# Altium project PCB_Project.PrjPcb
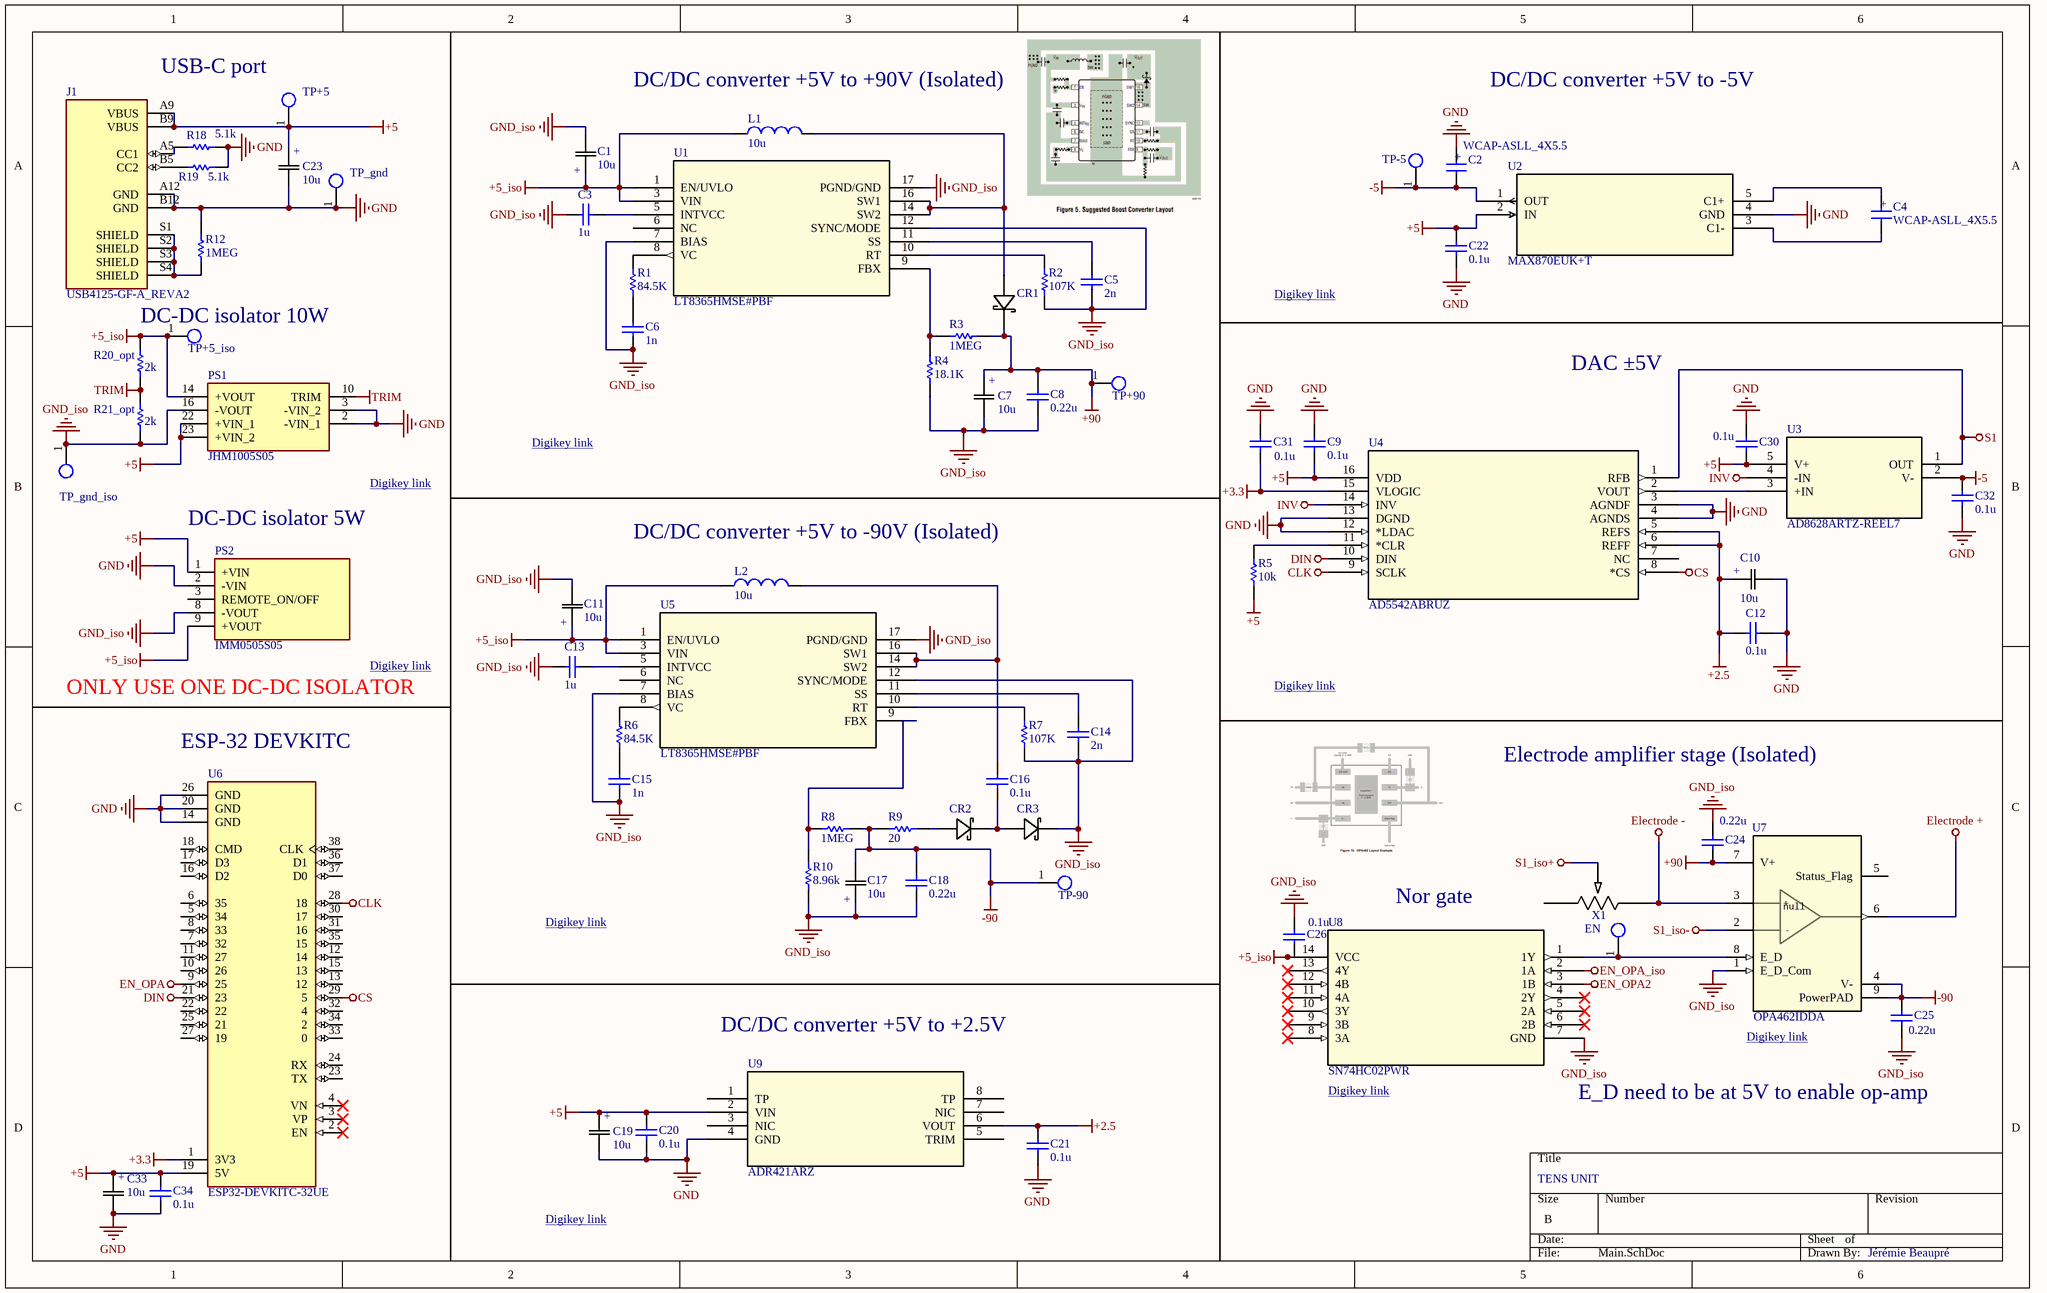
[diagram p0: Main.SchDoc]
3 sheets, 104 parts. Net scope: global (net labels, ports and power ports of the same name join across sheets).
Board file: PCB1.PcbDoc
Sheets:
  Main.SchDoc
  Current_check.SchDoc
  Isolation.SchDoc

## Sheet Main.SchDoc
size B; SheetNumber: 1; SheetTotal: 3

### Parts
C1  10u  [CAP_BX_10x20_RUB]
C2  WCAP-ASLL_4X5.5  [WCAP-ASLL_4X5.5(DXL)]
C3  value 1u  [0805_AVX]  (hidden comment: Capacitor)
C4  WCAP-ASLL_4X5.5  [WCAP-ASLL_4X5.5(DXL)]
C5  value 2n  [CAPC2012X75N]  (hidden comment: Capacitor)
C6  value 1n  [CC0805N_YAG]  (hidden comment: Capacitor)
C7  10u  [CAP_BX_10x20_RUB]
C8  value 0.22u  [CAP_C3225X7R2E224K200AA]  (hidden comment: Capacitor)
C9  value 0.1u  [CAPC2012X150N]  (hidden comment: Capacitor)
C10  10u  [CAP_BX_10x20_RUB]
C11  10u  [CAP_BX_10x20_RUB]
C12  value 0.1u  [CAPC2012X150N]  (hidden comment: Capacitor)
C13  value 1u  [0805_AVX]  (hidden comment: Capacitor)
C14  value 2n  [CAPC2012X75N]  (hidden comment: Capacitor)
C15  value 1n  [CC0805N_YAG]  (hidden comment: Capacitor)
C16  value 0.1u  [CAPC2012X150N]  (hidden comment: Capacitor)
C17  10u  [CAP_BX_10x20_RUB]
C18  value 0.22u  [CAP_C3225X7R2E224K200AA]  (hidden comment: Capacitor)
C19  10u  [CAP_BX_10x20_RUB]
C20  value 0.1u  [CAPC2012X150N]  (hidden comment: Capacitor)
C21  value 0.1u  [CAPC2012X150N]  (hidden comment: Capacitor)
C22  value 0.1u  [CAPC2012X150N]  (hidden comment: Capacitor)
C23  10u  [CAP_BX_10x20_RUB]
C24  value 0.22u  [CAP_C3225X7R2E224K200AA]  (hidden comment: Capacitor)
C25  value 0.22u  [CAP_C3225X7R2E224K200AA]  (hidden comment: Capacitor)
C26  value 0.1u  [CAPC2012X150N]  (hidden comment: Capacitor)
C30  value 0.1u  [CAPC2012X150N]  (hidden comment: Capacitor)
C31  value 0.1u  [CAPC2012X150N]  (hidden comment: Capacitor)
C32  value 0.1u  [CAPC2012X150N]  (hidden comment: Capacitor)
C33  10u  [CAP_BX_10x20_RUB]
C34  value 0.1u  [CAPC2012X150N]  (hidden comment: Capacitor)
CR1  SK220ATR  [DIODE_SK220ATR_SMC-M]  (value not drawn)
CR2  SK220ATR  [DIODE_SK220ATR_SMC-M]  (value not drawn)
CR3  SK220ATR  [DIODE_SK220ATR_SMC-M]  (value not drawn)
EN  Testpoint_1  [Testpoint1]  (value not drawn)  (no BOM)
J1  USB4125-GF-A_REVA2  [GCT_USB4125-GF-A_REVA2]
L1  value 10u  [DR73]  (hidden comment: Inductor)
L2  value 10u  [DR73]  (hidden comment: Inductor)
PS1  JHM1005S05  [JHM1005S05]
PS2  IMM0505S05  [IMM0505S05]
R1  value 84.5K  [Resistor_0805-M]  (hidden comment: Resistor)
R2  value 107K  [Resistor_0805-M]  (hidden comment: Resistor)
R3  value 1MEG  [Resistor_0805-M]  (hidden comment: Resistor)
R4  value 18.1K  [Resistor_0805-M]  (hidden comment: Resistor)
R5  value 10k  [Resistor_0805-M]  (hidden comment: Resistor)
R6  value 84.5K  [Resistor_0805-M]  (hidden comment: Resistor)
R7  value 107K  [Resistor_0805-M]  (hidden comment: Resistor)
R8  1MEG  [Resistor_0805-M]
R9  value 20  [Resistor_0805-M]  (hidden comment: Resistor)
R10  value 8.96k  [Resistor_0805-M]  (hidden comment: Resistor)
R12  value 1MEG  [Resistor_0805-M]  (hidden comment: Resistor)
R18  value 5.1k  [Resistor_0805-M]  (hidden comment: Resistor)
R19  value 5.1k  [Resistor_0805-M]  (hidden comment: Resistor)
R20_opt  value 2k  [Resistor_0805-M]  (hidden comment: Resistor)
R21_opt  value 2k  [Resistor_0805-M]  (hidden comment: Resistor)
TP+5  Testpoint_1  [Testpoint1]  (value not drawn)  (no BOM)
TP+5_iso  Testpoint_1  [Testpoint1]  (value not drawn)  (no BOM)
TP+90  Testpoint_1  [Testpoint1]  (value not drawn)  (no BOM)
TP-5  Testpoint_1  [Testpoint1]  (value not drawn)  (no BOM)
TP-90  Testpoint_1  [Testpoint1]  (value not drawn)  (no BOM)
TP_gnd  Testpoint_1  [Testpoint1]  (value not drawn)  (no BOM)
TP_gnd_iso  Testpoint_1  [Testpoint1]  (value not drawn)  (no BOM)
U1  LT8365HMSE#PBF  [05-08-1871_ADI]
U2  MAX870EUK+T  [21-0057F_MXM]
U3  AD8628ARTZ-REEL7  [RJ_5_ADI]
U4  AD5542ABRUZ  [RU_16_ADI]
U5  LT8365HMSE#PBF  [05-08-1871_ADI]
U6  ESP32-DEVKITC-32UE  [ESPRESSIF_ESP32-DEVKITC-32UE]
U7  OPA462IDDA  [DDA0008J-IPC_A]
U8  SN74HC02PWR  [PW14]
U9  ADR421ARZ  [R_8_ADI]
X1  PV36W102C01B00  [POT_PV36W_MUR]  (value not drawn)

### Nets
+2.5: C10.1(+) C12.2 C21.2 U4.5(REFS) U4.6(REFF) U9.6(VOUT)
+3.3: C31.2 U4.15(VLOGIC) U6.1(3V3)
+5: C9.2 C19.1(+) C20.2 C22.1 C23.1(+) C30.2 C33.1(+) C34.2 J1.A9(VBUS) J1.B9(VBUS) PS1.22(+VIN_1) PS1.23(+VIN_2) PS2.1(+VIN) R5.1 TP+5.1(P1) U2.2(IN) U3.5(V+) U4.16(VDD) U6.19(5V) U9.2(VIN)
+5_iso: C1.1(+) C11.1(+) C26.1 L1.1 L2.1 PS1.14(+VOUT) PS2.9(+VOUT) R20_opt.1 TP+5_iso.1(P1) U1.1(EN/UVLO) U1.3(VIN) U5.1(EN/UVLO) U5.3(VIN) U8.14(VCC)
+90: C7.1(+) C8.2 C24.2 CR1.1 R3.2 TP+90.1(P1) U7.7(V+)
-5: C2.2(NEG) C32.2 TP-5.1(P1) U2.1(OUT) U3.2(V-)
-90: C17.2 C18.2 C25.1 R8.1 R9.2 TP-90.1(P1) U7.4(V-) U7.9(PowerPAD)
CLK: U4.9(SCLK) U6.28(18)
CS: U4.8(*CS) U6.29(5)
DIN: U4.10(DIN) U6.21(23)
Electrode +: U7.6(OUT)
Electrode -: U7.3(+IN) X1.3
EN_OPA: U6.9(25)
EN_OPA2: U8.3(1B)
EN_OPA_iso: U8.2(1A)
GND: C2.1(POS) C9.1 C10.2 C12.1 C19.2 C20.1 C21.1 C22.2 C23.2 C30.1 C31.1 C32.1 C33.2 C34.1 J1.A12(GND) J1.B12(GND) PS1.2(-VIN_1) PS1.3(-VIN_2) PS2.2(-VIN) R12.2 R18.1 R19.1 TP_gnd.1(P1) U2.4(GND) U4.3(AGNDF) U4.4(AGNDS) U4.12(*LDAC) U4.13(DGND) U6.14(GND) U6.20(GND) U6.26(GND) U9.4(GND)
GND_iso: C1.2 C3.2 C5.1 C6.1 C7.2 C8.1 C11.2 C13.2 C14.1 C15.1 C17.1(+) C18.1 C24.1 C25.2 C26.2 CR3.1 PS1.16(-VOUT) PS2.8(-VOUT) R2.1 R4.2 R7.1 R10.2 R21_opt.2 TP_gnd_iso.1(P1) U1.7(BIAS) U1.12(SYNC/MODE) U1.17(PGND/GND) U5.7(BIAS) U5.12(SYNC/MODE) U5.17(PGND/GND) U7.1(E_D_Com) U8.7(GND)
INV: U3.4(-IN) U4.14(INV)
S1: U3.1(OUT) U4.1(RFB)
S1_iso+: X1.2
S1_iso-: U7.2(-IN)
TRIM: PS1.10(TRIM) R20_opt.2 R21_opt.1
NetC3_1: C3.1 U1.5(INTVCC)
NetC4_1: C4.1(POS) U2.5(C1+)
NetC4_2: C4.2(NEG) U2.3(C1-)
NetC5_2: C5.2 U1.11(SS)
NetC6_2: C6.2 R1.1
NetC13_1: C13.1 U5.5(INTVCC)
NetC14_2: C14.2 U5.11(SS)
NetC15_2: C15.2 R6.1
NetC16_1: C16.1 CR2.1 CR3.2
NetC16_2: C16.2 L2.2 U5.14(SW2) U5.16(SW1)
NetCR1_2: CR1.2 L1.2 U1.14(SW2) U1.16(SW1)
NetCR2_2: CR2.2 R9.1
NetEN_1: EN.1(P1) U7.8(E_D) U8.1(1Y)
NetJ1_A5: J1.A5(CC1) R18.2
NetJ1_B5: J1.B5(CC2) R19.2
NetJ1_S1: J1.S1(SHIELD) J1.S2(SHIELD) J1.S3(SHIELD) J1.S4(SHIELD) R12.1
NetR1_2: R1.2 U1.8(VC)
NetR2_2: R2.2 U1.10(RT)
NetR3_1: R3.1 R4.1 U1.9(FBX)
NetR5_2: R5.2 U4.11(*CLR)
NetR6_2: R6.2 U5.8(VC)
NetR7_2: R7.2 U5.10(RT)
NetR8_2: R8.2 R10.1 U5.9(FBX)
NetU3_3: U3.3(+IN) U4.2(VOUT)

Not connected (* = marked no-connect by the designer): PS2 3(REMOTE_ON/OFF); U1 6(NC); U4 7(NC); U5 6(NC); U6 2(EN)* 3(VP)* 4(VN)* 5(34) 6(35) 7(32) 8(33) 10(26) 11(27) 12(14) 13(12) 15(13) 16(D2) 17(D3) 18(CMD) 22 23(TX) 24(RX) 25(21) 27(19) 30(17) 31(16) 32(4) 33(0) 34(2) 35(15) 36(D1) 37(D0) 38(CLK); U7 5(Status_Flag); U8 4(2Y)* 5(2A)* 6(2B)* 8(3A)* 9(3B)* 10(3Y)* 11(4A)* 12(4B)* 13(4Y)*; U9 1(TP) 3(NIC) 5(TRIM) 7(NIC) 8(TP); X1 1

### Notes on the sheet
- USB-C port
- (near L1) DC/DC converter +5V to +90V (Isolated)
- DC/DC converter +5V to -5V
- Digikey link <https://www.digikey.ca/en/products/detail/analog-devices-inc-maxim-integrated/MAX870EUK-T/1519059?_gl=1*bc40r*_up*MQ..*_gs*MQ..&gclid=Cj0KCQjwm8bTBhDWARIsAC9Hi8lZmiOB0El9-E_6c1ow4nDcjeTHfbqA0Lnjgy8U8yTUWBJwg5PWeQ0aAiB7EALw_wcB&gclsrc=aw.ds&gbraid=0AAAAADrbLlh2Yqokbm2Ifr7gOHjBvqx8v>
- (near TP+5_iso) DC-DC isolator 10W
- DAC ±5V
- Digikey link <https://www.digikey.ca/en/products/detail/xp-power/JHM1005S05/4488429?s=N4IgTCBcDaIFYAsC2BGADGgrAZyyAugL5A>
- Digikey link <https://www.digikey.ca/en/products/detail/analog-devices-inc/LT8365HMSE-PBF/11586882?_gl=1*1sgahmh*_up*MQ..*_gs*MQ..&gclid=Cj0KCQjwm8bTBhDWARIsAC9Hi8lZmiOB0El9-E_6c1ow4nDcjeTHfbqA0Lnjgy8U8yTUWBJwg5PWeQ0aAiB7EALw_wcB&gclsrc=aw.ds&gbraid=0AAAAADrbLlh2Yqokbm2Ifr7gOHjBvqx8v>
- (near PS2) DC-DC isolator 5W
- (near L2) DC/DC converter +5V to -90V (Isolated)
- (near PS2) ONLY USE ONE DC-DC ISOLATOR
- Digikey link <https://www.digikey.ca/en/products/detail/xp-power/IMM0505S05/9843481>
- Digikey link <https://www.digikey.ca/en/products/detail/analog-devices-inc/AD5542ABRUZ/2506909?_gl=1*iimu8l*_up*MQ..*_gs*MQ..&gclid=Cj0KCQjwm8bTBhDWARIsAC9Hi8lZmiOB0El9-E_6c1ow4nDcjeTHfbqA0Lnjgy8U8yTUWBJwg5PWeQ0aAiB7EALw_wcB&gclsrc=aw.ds&gbraid=0AAAAADrbLlh2Yqokbm2Ifr7gOHjBvqx8v>
- (near U6) ESP-32 DEVKITC
- Electrode amplifier stage (Isolated)
- Nor gate
- DC/DC converter +5V to +2.5V
- (near U7) Digikey link <https://www.digikey.ca/en/products/detail/texas-instruments/OPA462IDDA/11502197?_gl=1*15g1sy5*_up*MQ..*_gs*MQ..&gclid=Cj0KCQjwm8bTBhDWARIsAC9Hi8lZmiOB0El9-E_6c1ow4nDcjeTHfbqA0Lnjgy8U8yTUWBJwg5PWeQ0aAiB7EALw_wcB&gclsrc=aw.ds&gbraid=0AAAAADrbLlh2Yqokbm2Ifr7gOHjBvqx8v>
- (near U8) Digikey link <https://www.digikey.ca/en/products/detail/texas-instruments/SN74HC02PWR/377046?_gl=1*15g1sy5*_up*MQ..*_gs*MQ..&gclid=Cj0KCQjwm8bTBhDWARIsAC9Hi8lZmiOB0El9-E_6c1ow4nDcjeTHfbqA0Lnjgy8U8yTUWBJwg5PWeQ0aAiB7EALw_wcB&gclsrc=aw.ds&gbraid=0AAAAADrbLlh2Yqokbm2Ifr7gOHjBvqx8v>
- E_D need to be at 5V to enable op-amp
- TENS UNIT
- Digikey link <https://www.digikey.ca/en/products/detail/analog-devices-inc/ADR421ARZ/936588?_gl=1*1nl2uwz*_up*MQ..*_gs*MQ..&gclid=Cj0KCQjwm8bTBhDWARIsAC9Hi8lZmiOB0El9-E_6c1ow4nDcjeTHfbqA0Lnjgy8U8yTUWBJwg5PWeQ0aAiB7EALw_wcB&gclsrc=aw.ds&gbraid=0AAAAADrbLlh2Yqokbm2Ifr7gOHjBvqx8v>
- Jérémie Beaupré

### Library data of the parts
C1 C7 C10 C11 C17 C19 C23 C33 = 450BXC10MEFC10X20: No Description Available; Manufacturer_Name: Rubycon
C2 C4 = WCAP-ASLL_4X5.5: MF: {'manufacturer': u'W\xfcrth Elektronik'}; MP: 865060640001
C3 C5 C6 C8 C9 C12-C16 C18 C20-C22 C24-C26 C30-C32 C34 = Capacitor: SimulationGenericComponent: True
CR1-CR3 = SK220ATR: No Description Available; Manufacturer_Name: SMC Diode Solutions
L1 L2 = Inductor: SimulationGenericComponent: True
PS1 = JHM1005S05: Power Supply; Manufacturer_Name: XP POWER
PS2 = IMM0505S05: Power Supply; Manufacturer_Name: XP POWER
R1-R10 R12 R18 R19 R20_opt R21_opt = Resistor: TC1: 0; SimulationGenericComponent: True
U1 U5 = LT8365HMSEPBF: Low IQ Boost/SEPIC/Inverting Converter with 1.5A, 150V SwitchÂ; Manufacturer_Name: Analog Devices Inc
U2 = MAX870EUK+T: Switched-Capacitor Voltage Inverters; Manufacturer_Name: Analog Devices Inc
U3 = AD8628ARTZ-REEL7: Zero-Drift, Single-Supply, Rail-to-Rail Input/Output Operational Amplifier; Manufacturer_Name: Analog Devices Inc
U4 = AD5542ABRUZ: 2.7 V to 5.5 V, Serial-Input, Voltage-Output, 16-Bit nanoDACâ„¢ in 10-lead LFCSP, 16-lead 3 mm x 3 mm LFCSP, and 16-lead TSSOP; Manufacturer_Name: Analog Devices Inc
U6 = ESP32-DEVKITC-32UE: The ESP32-DEVKITC-32UE evaluation board from Espressif Systems is designed for seamless wireless connectivity in IoT applications. Powered by the ESP32-WROOM-32UE module, it supports dual-mode BluetoothÂ® Smart Ready 4.x and 802.11 b/g/n Wi-Fi at 2.4GHz.
U7 = OPA462IDDA: 180-V, wide bandwidth (6.5 MHz), high-slew rate (25 V/Âµs) unity-gain stable op amp 8-SO PowerPAD -40 to 85; Manufacturer_Name: Texas Instruments
U8 = SN74HC02PWR: 4-ch, 2-input, 2-V to 6-V 5.2 mA drive strength NOR gate 14-TSSOP -40 to 85; Manufacturer_Name: Texas Instruments
U9 = ADR421ARZ: Ultraprecision, Low Noise, 2.500 V XFETÂ® Voltage References; Manufacturer_Name: Analog Devices Inc
X1 = PV36W102C01B00: No Description Available; Manufacturer_Name: Murata

## Sheet Current_check.SchDoc
size A; SheetNumber: 2; SheetTotal: 3
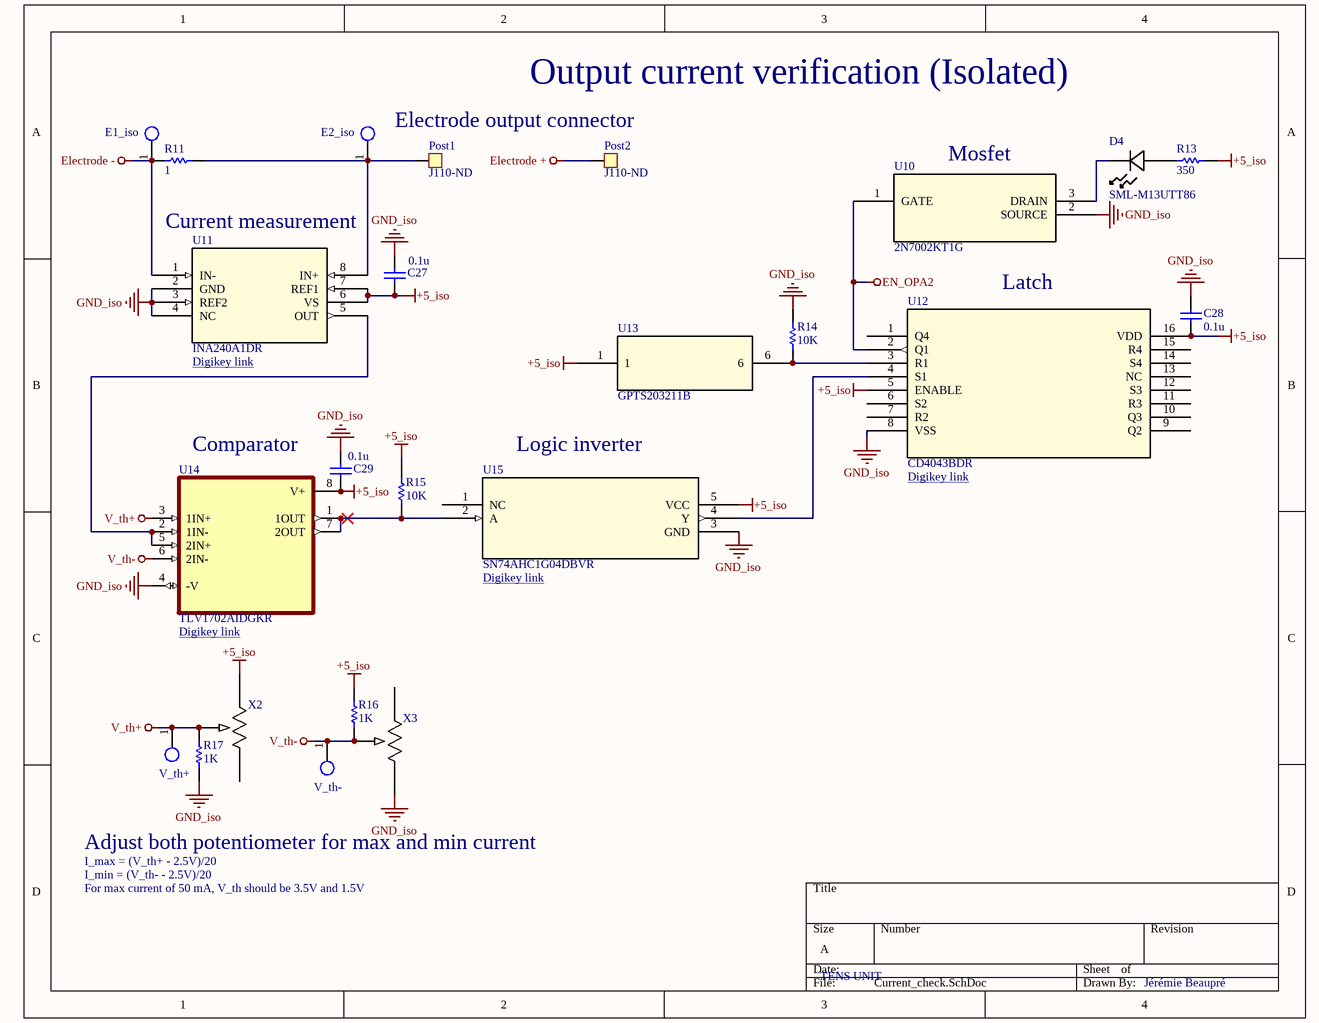
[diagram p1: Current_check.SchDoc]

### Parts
C27  value 0.1u  [CAPC2012X150N]  (hidden comment: Capacitor)
C28  value 0.1u  [CAPC2012X150N]  (hidden comment: Capacitor)
C29  value 0.1u  [CAPC2012X150N]  (hidden comment: Capacitor)
D4  SML-M13UTT86  [LED_SML-M13DT_ROM]
E1_iso  Testpoint_1  [Testpoint1]  (value not drawn)  (no BOM)
E2_iso  Testpoint_1  [Testpoint1]  (value not drawn)  (no BOM)
Post1  J110-ND  [J110-ND]
Post2  J110-ND  [J110-ND]
R11  value 1  [Resistor_0805-M]  (hidden comment: Resistor)
R13  value 350  [Resistor_0805-M]  (hidden comment: Resistor)
R14  value 10K  [Resistor_0805-M]  (hidden comment: Resistor)
R15  value 10K  [Resistor_0805-M]  (hidden comment: Resistor)
R16  value 1K  [Resistor_0805-M]  (hidden comment: Resistor)
R17  value 1K  [Resistor_0805-M]  (hidden comment: Resistor)
U10  2N7002KT1G  [SOT-23_ONS]
U11  INA240A1DR  [D8_TEX]
U12  CD4043BDR  [D16]
U13  GPTS203211B  [SWITCH_03211B]
U14  TLV1702AIDGKR  [SOP65P490X110-8N]
U15  SN74AHC1G04DBVR  [DBV5]
V_th+  Testpoint_1  [Testpoint1]  (value not drawn)  (no BOM)
V_th-  Testpoint_1  [Testpoint1]  (value not drawn)  (no BOM)
X2  PV36W102C01B00  [POT_PV36W_MUR]  (value not drawn)
X3  PV36W102C01B00  [POT_PV36W_MUR]  (value not drawn)

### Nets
+5_iso: C27.2 C28.2 C29.2 R13.2 R15.2 R16.2 U11.6(VS) U11.7(REF1) U12.5(ENABLE) U12.16(VDD) U13.1 U14.8(V+) U15.5(VCC) X2.3
Electrode +: Post2.1
Electrode -: E1_iso.1(P1) R11.1 U11.1(IN-)
EN_OPA2: U10.1(GATE) U12.2(Q1)
GND_iso: C27.1 C28.1 C29.1 R14.2 R17.1 U10.2(SOURCE) U11.2(GND) U11.3(REF2) U11.4(NC) U12.8(VSS) U14.4(-V) U15.3(GND) X3.1
V_th+: R17.2 U14.3(1IN+) V_th+.1(P1) X2.2
V_th-: R16.1 U14.6(2IN-) V_th-.1(P1) X3.2
NetD4_1: D4.1 U10.3(DRAIN)
NetD4_2: D4.2 R13.1
NetE2_iso_1: E2_iso.1(P1) Post1.1 R11.2 U11.8(IN+)
NetR14_1: R14.1 U12.3(R1) U13.6
NetR15_1: R15.1 U14.1(1OUT) U14.7(2OUT) U15.2(A)
NetU11_5: U11.5(OUT) U14.2(1IN-) U14.5(2IN+)
NetU12_4: U12.4(S1) U15.4(Y)

Not connected (* = marked no-connect by the designer): U12 1(Q4) 6(S2) 7(R2) 9(Q2) 10(Q3) 11(R3) 12(S3) 13(NC) 14(S4) 15(R4); U15 1(NC); X2 1; X3 3

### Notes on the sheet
- Output current verification (Isolated)
- Electrode output connector
- (near U10) Mosfet
- Current measurement
- Latch
- (near U11) Digikey link <https://www.digikey.ca/en/products/detail/texas-instruments/INA240A1DR/8538109?_gl=1*1puq8vm*_up*MQ..*_gs*MQ..&gclid=Cj0KCQjwm8bTBhDWARIsAC9Hi8lZmiOB0El9-E_6c1ow4nDcjeTHfbqA0Lnjgy8U8yTUWBJwg5PWeQ0aAiB7EALw_wcB&gclsrc=aw.ds&gbraid=0AAAAADrbLlh2Yqokbm2Ifr7gOHjBvqx8v>
- Comparator
- Logic inverter
- (near U12) Digikey link <https://www.digikey.ca/en/products/detail/texas-instruments/CD4043BDR/1691049?_gl=1*2ig6y2*_up*MQ..*_gs*MQ..&gclid=Cj0KCQjwm8bTBhDWARIsAC9Hi8lZmiOB0El9-E_6c1ow4nDcjeTHfbqA0Lnjgy8U8yTUWBJwg5PWeQ0aAiB7EALw_wcB&gclsrc=aw.ds&gbraid=0AAAAADrbLlh2Yqokbm2Ifr7gOHjBvqx8v>
- Digikey link <https://www.digikey.ca/en/products/detail/texas-instruments/TLV1702AIDGKR/4555458?_gl=1*2ig6y2*_up*MQ..*_gs*MQ..&gclid=Cj0KCQjwm8bTBhDWARIsAC9Hi8lZmiOB0El9-E_6c1ow4nDcjeTHfbqA0Lnjgy8U8yTUWBJwg5PWeQ0aAiB7EALw_wcB&gclsrc=aw.ds&gbraid=0AAAAADrbLlh2Yqokbm2Ifr7gOHjBvqx8v>
- (near U15) Digikey link <https://www.digikey.ca/en/products/detail/texas-instruments/SN74AHC1G04DBVR/276733?_gl=1*2ig6y2*_up*MQ..*_gs*MQ..&gclid=Cj0KCQjwm8bTBhDWARIsAC9Hi8lZmiOB0El9-E_6c1ow4nDcjeTHfbqA0Lnjgy8U8yTUWBJwg5PWeQ0aAiB7EALw_wcB&gclsrc=aw.ds&gbraid=0AAAAADrbLlh2Yqokbm2Ifr7gOHjBvqx8v>
- Adjust both potentiometer for max and min current
- I_max = (V_th+ - 2.5V)/20
- I_min = (V_th- - 2.5V)/20
- For max current of 50 mA, V_th should be 3.5V and 1.5V
- TENS UNIT
- Jérémie Beaupré

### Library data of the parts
C27-C29 = Capacitor: SimulationGenericComponent: True
D4 = SML-M13UTT86: No Description Available; Manufacturer_Name: ROHM Semiconductor
R11 R13-R17 = Resistor: TC1: 0; SimulationGenericComponent: True
U10 = 2N7002KT1G: Description; Manufacturer_Name: onsemi
U11 = INA240A1DR: -4 to 80V, bidirectional, ultra-precise current sense amplifier with enhanced PWM rejection 8-SOIC -40 to 125; Manufacturer_Name: Texas Instruments
U12 = CD4043BDR: CMOS Quad NOR R/S Latch with 3-State Outputs 16-SOIC -55 to 125; Manufacturer_Name: Texas Instruments
U13 = GPTS203211B: No Description Available; Manufacturer_Name: CW Industries
U14 = TLV1702AIDGKR: Dual high voltage, low power comparator; MF: Texas Instruments
U15 = SN74AHC1G04DBVR: Single 2-V to 5.5-V inverter 5-SOT-23 -40 to 125; Manufacturer_Name: Texas Instruments
X2 X3 = PV36W102C01B00: as X1 on sheet Main

## Sheet Isolation.SchDoc
size A; SheetNumber: 3; SheetTotal: 3
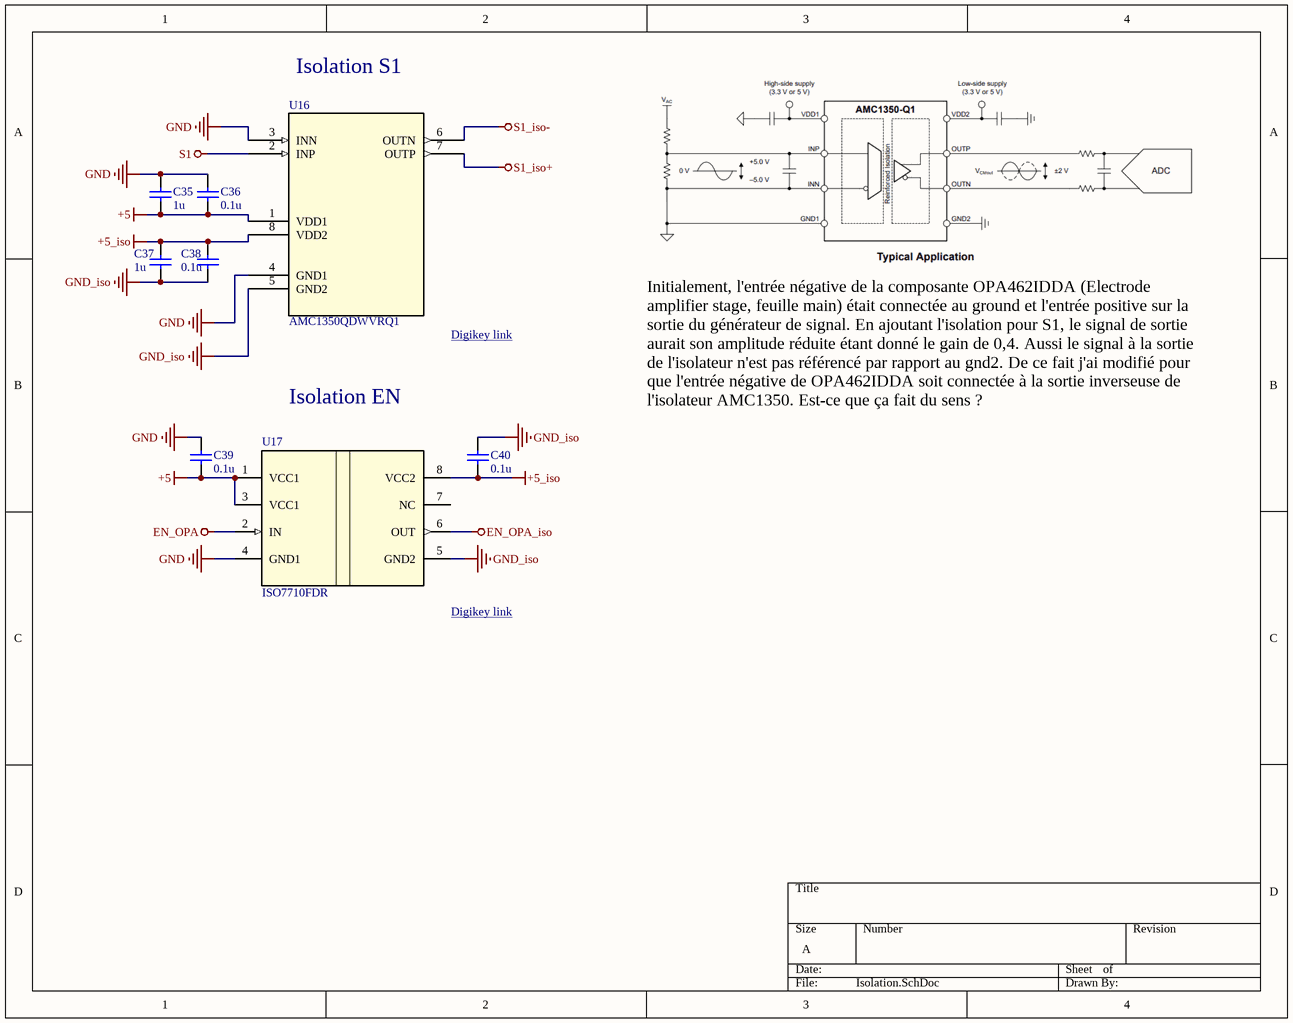
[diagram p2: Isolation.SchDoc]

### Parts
C35  value 1u  [0805_AVX]  (hidden comment: Capacitor)
C36  value 0.1u  [CAPC2012X150N]  (hidden comment: Capacitor)
C37  value 1u  [0805_AVX]  (hidden comment: Capacitor)
C38  value 0.1u  [CAPC2012X150N]  (hidden comment: Capacitor)
C39  value 0.1u  [CAPC2012X150N]  (hidden comment: Capacitor)
C40  value 0.1u  [CAPC2012X150N]  (hidden comment: Capacitor)
U16  AMC1350QDWVRQ1  [AMC1350QDWVRQ1_TEX]
U17  ISO7710FDR  [D0008B_N]

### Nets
+5: C35.2 C36.1 C39.2 U16.1(VDD1) U17.1(VCC1) U17.3(VCC1)
+5_iso: C37.1 C38.2 C40.2 U16.8(VDD2) U17.8(VCC2)
EN_OPA: U17.2(IN)
EN_OPA_iso: U17.6(OUT)
GND: C35.1 C36.2 C39.1 U16.3(INN) U16.4(GND1) U17.4(GND1)
GND_iso: C37.2 C38.1 C40.1 U16.5(GND2) U17.5(GND2)
S1: U16.2(INP)
S1_iso+: U16.7(OUTP)
S1_iso-: U16.6(OUTN)

Not connected (* = marked no-connect by the designer): U17 7(NC)

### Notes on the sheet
- Isolation S1
- (near U16) Digikey link <https://www.digikey.ca/en/products/detail/texas-instruments/AMC1350QDWVRQ1/16184258?gclsrc=aw.ds&gad_source=1&gad_campaignid=23536462204&gbraid=0AAAAADrbLlgPIMavqT0FMg8RnG3SAJlVn&gclid=CjwKCAjwtp7VBhBjEiwAJfpV-7trzx5dm_GJ_BDihVdM6MrJPevNCHBW8ri5qEOeuZCw5XcXnlMmKhoCRM0QAvD_BwE>
- Isolation EN
- Initialement, l'entrée négative de la composante OPA462IDDA (Electrode amplifier stage, feuille main) était connectée au ground et l'entrée positive sur la sortie du générateur de signal. En ajoutant l'isolation pour S1, le signal de sortie aurait son amplitude réduite étant donné le gain de 0,4. Aussi le signal à la sortie de l'isolateur n'est pas référencé par rapport au gnd2. De ce fait j'ai modifié pour que l'entrée négative de OPA462IDDA soit connectée à la sortie inverseuse de l'isolateur AMC1350. Est-ce que ça fait du sens ?
- Digikey link <https://www.digikey.ca/en/products/detail/texas-instruments/ISO7710FDR/7173733>

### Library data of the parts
C35-C40 = Capacitor: SimulationGenericComponent: True
U16 = AMC1350QDWVRQ1: Automotive, &plusmn;5-V input, precision voltage sensing reinforced isolated amplifier 8-SOIC -40 to 125; Manufacturer_Name: Texas Instruments
U17 = ISO7710FDR: Robust EMC, single-channel, reinforced digital isolator 8-SOIC -55 to 125; Manufacturer_Name: Texas Instruments

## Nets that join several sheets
+5: Main (20 pins), Isolation (6 pins)
+5_iso: Main (14 pins), Current_check (14 pins), Isolation (5 pins)
Electrode +: Main (U7.6), Current_check (Post2.1)
Electrode -: Main (U7.3 X1.3), Current_check (E1_iso.1 R11.1 U11.1)
EN_OPA: Main (U6.9), Isolation (U17.2)
EN_OPA2: Main (U8.3), Current_check (U10.1 U12.2)
EN_OPA_iso: Main (U8.2), Isolation (U17.6)
GND: Main (32 pins), Isolation (6 pins)
GND_iso: Main (32 pins), Current_check (13 pins), Isolation (5 pins)
S1: Main (U3.1 U4.1), Isolation (U16.2)
S1_iso+: Main (X1.2), Isolation (U16.7)
S1_iso-: Main (U7.2), Isolation (U16.6)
